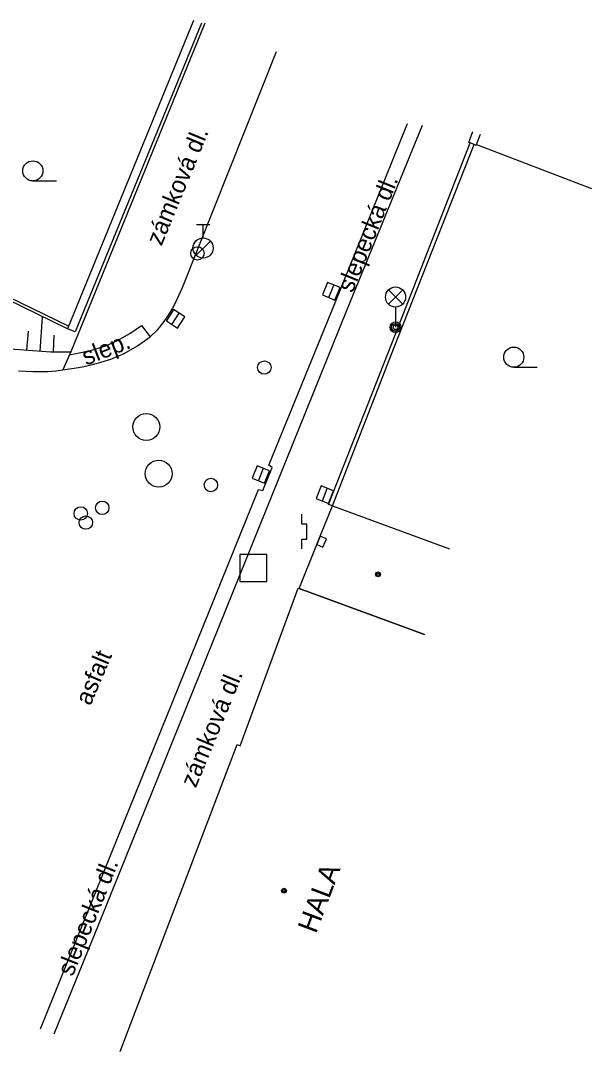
# Model space of a CAD drawing. Extents: x -643782 to -643673, y -1190834 to -1190720.
# Drawn here: x -643694.46 to -643673.23, y -1190804.15 to -1190765.79 of the extents above; entities that cross this region are included whole.
import ezdxf

# ---------------------------------------------------------------- set-up
doc = ezdxf.new("R2010")
doc.units = 0
for name, color, linetype in [('Bodové objekty elektro', 7, 'Continuous'), ('Bodové objekty kanalizace', 7, 'Continuous'), ('Bodové objekty katastrální', 7, 'Continuous'), ('Bodové objekty ostatní', 7, 'Continuous'), ('Bodové objekty plynovody', 7, 'Continuous'), ('Bodové objekty polohopis', 7, 'Continuous'), ('Bodové objekty vodovody', 7, 'Continuous'), ('Bodové objekty značky budov', 7, 'Continuous'), ('Bodové objekty značky předmětů', 7, 'Continuous'), ('BV_ČÍSLO', 7, 'Continuous'), ('Osa kolejí', 7, 'Continuous'), ('PB_VÝŠKA', 7, 'Continuous'), ('PBPP_VÝŠKA', 7, 'Continuous'), ('PBPP_ZNAČKA', 7, 'Continuous'), ('Popis povrchů', 7, 'Continuous'), ('Voda', 7, 'Continuous'), ('Šrafy', 7, 'Continuous')]:
    doc.layers.add(name, color=color, linetype=linetype)

msp = doc.modelspace()

# ---------------------------------------------------------------- linework, layer by layer
at = {"layer": 'Bodové objekty elektro'}
for p, q in [((-643683.999, -1190784.529), (-643684, -1190784.161)), ((-643683.816, -1190784.53), (-643683.999, -1190784.529)), ((-643683.816, -1190785.082), (-643683.816, -1190784.53)), ((-643684, -1190785.45), (-643683.999, -1190785.082)), ((-643683.999, -1190785.082), (-643683.816, -1190785.082))]:
    msp.add_line(p, q, dxfattribs=at)
at = {"layer": 'Bodové objekty kanalizace'}
for p, q in [((-643682.995, -1190776.091), (-643682.805, -1190775.629)), ((-643688.826, -1190777.099), (-643688.554, -1190776.681)), ((-643685.613, -1190782.912), (-643685.427, -1190782.448)), ((-643683.232, -1190783.662), (-643683.048, -1190783.198))]:
    msp.add_line(p, q, dxfattribs=at)
for points in [[(-643682.764, -1190776.186), (-643682.574, -1190775.724), (-643683.036, -1190775.534), (-643683.226, -1190775.996)], [(-643688.616, -1190777.236), (-643688.344, -1190776.816), (-643688.764, -1190776.544), (-643689.036, -1190776.964)], [(-643685.381, -1190783.005), (-643685.195, -1190782.541), (-643685.659, -1190782.355), (-643685.845, -1190782.819)], [(-643683, -1190783.754), (-643682.816, -1190783.29), (-643683.28, -1190783.106), (-643683.464, -1190783.57)]]:
    msp.add_lwpolyline(points, close=True, dxfattribs=at)
for centre in [(-643689.78, -1190780.91), (-643689.32, -1190782.65)]:
    msp.add_circle(centre, 0.5, dxfattribs=at)
at = {"layer": 'Bodové objekty katastrální'}
for p, q in [((-643694.002, -1190771.754), (-643693.127, -1190771.754)), ((-643676.112, -1190778.688), (-643675.237, -1190778.688))]:
    msp.add_line(p, q, dxfattribs=at)
for centre in [(-643694.002, -1190771.379), (-643676.112, -1190778.313)]:
    msp.add_circle(centre, 0.375, dxfattribs=at)
at = {"layer": 'Bodové objekty ostatní'}
msp.add_lwpolyline([(-643686.3, -1190786.66), (-643685.3, -1190786.66), (-643685.3, -1190785.66), (-643686.3, -1190785.66)], close=True, dxfattribs=at)
at = {"layer": 'Bodové objekty plynovody'}
for centre in [(-643685.39, -1190778.7), (-643687.38, -1190783.07)]:
    msp.add_circle(centre, 0.25, dxfattribs=at)
at = {"layer": 'Bodové objekty polohopis'}
for p, q in [((-643680.775, -1190776.34), (-643680.245, -1190775.81)), ((-643680.775, -1190775.81), (-643680.245, -1190776.34)), ((-643680.51, -1190776.45), (-643680.51, -1190777.2))]:
    msp.add_line(p, q, dxfattribs=at)
for centre, radius in [((-643680.51, -1190776.075), 0.375), ((-643680.51, -1190777.2), 0.2), ((-643680.51, -1190777.2), 0.145), ((-643680.51, -1190777.2), 0.0876)]:
    msp.add_circle(centre, radius, dxfattribs=at)
at = {"layer": 'Bodové objekty vodovody'}
for p, q in [((-643687.92, -1190773.375), (-643687.42, -1190773.375)), ((-643687.67, -1190773.875), (-643687.67, -1190773.375)), ((-643687.928, -1190774.522), (-643687.398, -1190773.992))]:
    msp.add_line(p, q, dxfattribs=at)
for centre, radius in [((-643687.88, -1190774.45), 0.25), ((-643687.67, -1190774.25), 0.375), ((-643691.42, -1190783.92), 0.25), ((-643692.22, -1190784.13), 0.25), ((-643692.03, -1190784.47), 0.25)]:
    msp.add_circle(centre, radius, dxfattribs=at)
at = {"layer": 'Bodové objekty značky budov'}
for centre, radius in [((-643681.164, -1190786.394), 0.09), ((-643681.164, -1190786.394), 0.0398), ((-643684.661, -1190798.17), 0.09), ((-643684.661, -1190798.17), 0.0398)]:
    msp.add_circle(centre, radius, dxfattribs=at)
at = {"layer": 'BV_ČÍSLO'}
msp.add_line((-643680.65, -1190777.8), (-643677.74, -1190770.34), dxfattribs=at)
for points in [[(-643687.605, -1190765.882), (-643692.59, -1190778.11), (-643692.64, -1190778.23), (-643692.89, -1190778.79)], [(-643693.205, -1190803.493), (-643691.553, -1190799.413), (-643682.333, -1190776.603), (-643679.509, -1190769.675)], [(-643692.64, -1190778.23), (-643692.403, -1190778.175), (-643691.861, -1190778.062), (-643691.286, -1190777.891), (-643690.851, -1190777.695), (-643690.392, -1190777.437), (-643689.96, -1190777.13), (-643689.64, -1190777.56)], [(-643682.85, -1190783.85), (-643683.01, -1190783.8), (-643680.65, -1190777.8)]]:
    msp.add_lwpolyline(points, dxfattribs=at)
at = {"layer": 'Osa kolejí'}
msp.add_lwpolyline([(-643683.31, -1190784.98), (-643683.44, -1190785.29), (-643683.209, -1190785.387), (-643683.079, -1190785.077), (-643683.31, -1190784.98)], dxfattribs=at)
at = {"layer": 'PB_VÝŠKA'}
for points in [[(-643694.53, -1190778.82), (-643694, -1190778.85), (-643693.44, -1190778.85), (-643693.15, -1190778.82), (-643692.89, -1190778.79), (-643692.307, -1190778.698), (-643692.11, -1190778.66), (-643691.731, -1190778.578), (-643691.47, -1190778.5), (-643691.1, -1190778.39), (-643690.84, -1190778.28), (-643690.611, -1190778.17), (-643690.109, -1190777.888), (-643689.64, -1190777.56), (-643689.361, -1190777.29), (-643689.29, -1190777.21), (-643689.08, -1190776.93), (-643688.96, -1190776.75), (-643688.821, -1190776.526), (-643688.71, -1190776.32), (-643688.631, -1190776.16), (-643688.44, -1190775.72), (-643684.94, -1190766.94)], [(-643693.72, -1190803.31), (-643690.856, -1190796.218), (-643685.61, -1190783.24), (-643685.45, -1190783.28), (-643685.1, -1190782.42), (-643685.22, -1190782.33), (-643682.77, -1190776.31), (-643680.06, -1190769.62)]]:
    msp.add_lwpolyline(points, dxfattribs=at)
at = {"layer": 'PBPP_VÝŠKA'}
for p, q in [((-643677.511, -1190770.429), (-643677.354, -1190770.015)), ((-643692.67, -1190777.164), (-643694.896, -1190776.08))]:
    msp.add_line(p, q, dxfattribs=at)
for points in [[(-643688.029, -1190765.787), (-643692.708, -1190777.257)], [(-643687.73, -1190765.88), (-643692.43, -1190777.37), (-643692.708, -1190777.257)], [(-643677.511, -1190770.429), (-643677.59, -1190770.4), (-643677.74, -1190770.34), (-643677.79, -1190770.32), (-643677.634, -1190769.91)], [(-643682.85, -1190783.85), (-643680.55, -1190777.92), (-643677.59, -1190770.4)], [(-643677.5, -1190770.4), (-643673.226, -1190772.031)], [(-643692.708, -1190777.257), (-643694.94, -1190776.17), (-643694.896, -1190776.08)]]:
    msp.add_lwpolyline(points, dxfattribs=at)
at = {"layer": 'PBPP_ZNAČKA'}
for points in [[(-643679.438, -1190788.637), (-643684.1, -1190786.92), (-643683.44, -1190785.29), (-643683.31, -1190784.98), (-643682.85, -1190783.85), (-643678.506, -1190785.449)], [(-643690.75, -1190804.15), (-643686.4, -1190792.73), (-643686.288, -1190792.773), (-643684.13, -1190786.91), (-643684.1, -1190786.92), (-643679.438, -1190788.637)]]:
    msp.add_lwpolyline(points, dxfattribs=at)
at = {"layer": 'Voda'}
msp.add_lwpolyline([(-643697.2, -1190778.01), (-643695.98, -1190777.82), (-643694.67, -1190778.01), (-643693.33, -1190778.12), (-643692.59, -1190778.11)], dxfattribs=at)
at = {"layer": 'Šrafy'}
for p, q in [((-643693.732, -1190778.087), (-643693.647, -1190776.828)), ((-643694.23, -1190778.046), (-643694.163, -1190777.344)), ((-643693.233, -1190778.119), (-643693.205, -1190777.492))]:
    msp.add_line(p, q, dxfattribs=at)

# ---------------------------------------------------------------- texts
at = {"layer": 'Bodové objekty značky předmětů'}
msp.add_text('HALA', height=0.75, rotation=69.3748, dxfattribs=at).set_placement((-643683.471, -1190799.796))
at = {"layer": 'Popis povrchů'}
for s, height, rotation, p in [('zámková dl.', 0.64996, 67.5797, (-643689.218, -1190774.201)), ('slepecká dl.', 0.64999, 68.0617, (-643682.111, -1190775.947)), ('slep.', 0.65, 21.3638, (-643692.021, -1190778.628)), ('asfalt', 0.65, 66.9572, (-643691.86, -1190791.312)), ('zámková dl.', 0.64996, 67.5797, (-643687.943, -1190794.375)), ('slepecká dl.', 0.64999, 68.0617, (-643692.521, -1190801.39))]:
    msp.add_text(s, height=height, rotation=rotation, dxfattribs=at).set_placement(p)

doc.saveas('drawing.dxf')
